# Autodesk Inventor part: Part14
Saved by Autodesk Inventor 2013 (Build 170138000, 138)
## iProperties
Created: 2012-07
Part Number: Part14
Material: Generic
Document SubType Name: Modeling
Designer: Paul
Density: 1 g/cm^3
Author: Paul
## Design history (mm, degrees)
node "User Library-Arduino Mega.SAT1"
body "Solid1"
node "Base1"
